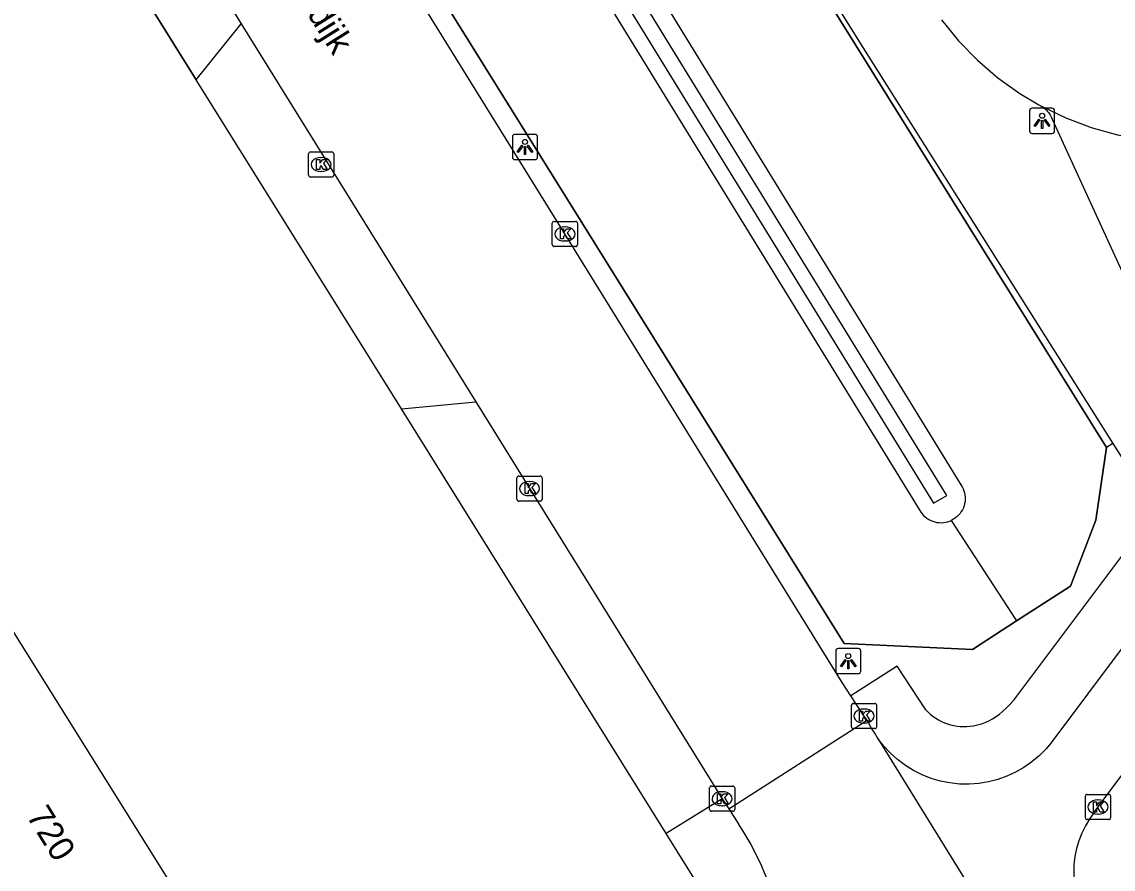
# Model space of a CAD drawing. Extents: x 158838 to 160074, y 386376 to 387776.
# Drawn here: x 159182.34 to 159225.69, y 386765.84 to 386799.5 of the extents above; entities that cross this region are included whole.
import ezdxf

# ---------------------------------------------------------------- set-up
doc = ezdxf.new("R2010")
doc.units = 0
for name, color, linetype in [('IMGEO_Berm_groen', 7, 'Continuous'), ('IMGEO_Fietspad_gesloten', 7, 'Continuous'), ('IMGEO_Groenvoorziening', 7, 'Continuous'), ('IMGEO_Hek', 7, 'Continuous'), ('IMGEO_Kolk', 7, 'Continuous'), ('IMGEO_Lichtpunt', 7, 'Continuous'), ('IMGEO_Openbare_ruimte_label', 7, 'Continuous'), ('IMGEO_OVBaan_gesloten', 7, 'Continuous'), ('IMGEO_Pand', 7, 'Continuous'), ('IMGEO_Pand_nummerreeks', 7, 'Continuous'), ('IMGEO_Rijbaan_lokaal_gesloten', 7, 'Continuous'), ('IMGEO_Rijbaan_lokaal_open', 7, 'Continuous'), ('IMGEO_Voetpad_open', 7, 'Continuous')]:
    doc.layers.add(name, color=color, linetype=linetype)

msp = doc.modelspace()

# ---------------------------------------------------------------- linework, layer by layer
at = {"layer": 'IMGEO_Berm_groen'}
for points in [[(159221.856, 386775.703), (159220.103, 386774.566), (159215.005, 386774.81), (159181.964, 386827.844)], [(159225.683, 386782.752), (159225.425, 386782.595)], [(159221.856, 386775.703), (159223.994, 386777.09), (159224.999, 386779.713), (159225.425, 386782.595)]]:
    msp.add_lwpolyline(points, dxfattribs=at)
at = {"layer": 'IMGEO_Fietspad_gesloten'}
for points in [[(159222.857, 386796.143), (159222.934, 386796.089), (159223.007, 386796.028), (159223.074, 386795.961), (159223.135, 386795.888), (159223.189, 386795.81), (159223.236, 386795.728), (159223.275, 386795.642), (159229.547, 386781.951), (159229.638, 386781.735), (159229.721, 386781.477), (159229.781, 386781.212), (159229.818, 386780.944), (159229.83, 386780.673), (159229.818, 386780.402), (159229.781, 386780.133), (159229.721, 386779.869), (159229.638, 386779.611), (159229.532, 386779.361)], [(159229.086, 386778.683), (159223.221, 386770.847), (159223.029, 386770.621), (159222.759, 386770.349), (159222.465, 386770.103), (159222.15, 386769.883), (159221.817, 386769.693), (159221.468, 386769.533), (159221.107, 386769.405), (159220.735, 386769.309), (159220.356, 386769.248), (159219.974, 386769.22), (159219.59, 386769.227), (159219.209, 386769.268), (159218.832, 386769.342), (159218.464, 386769.45), (159218.107, 386769.591), (159217.764, 386769.763), (159217.438, 386769.965), (159217.131, 386770.195), (159216.846, 386770.452), (159216.585, 386770.733), (159216.35, 386771.036)], [(159224.961, 386768.129), (159225.089, 386768.314), (159229.188, 386773.771)]]:
    msp.add_lwpolyline(points, dxfattribs=at)
msp.add_arc((159227.983, 386765.729), 3.859, 141.5421, 219.2626, dxfattribs=at)
at = {"layer": 'IMGEO_Groenvoorziening'}
for points in [[(159182.122, 386834.323), (159182.77, 386834.218), (159183.406, 386834.055), (159184.024, 386833.836), (159184.621, 386833.563), (159185.191, 386833.237), (159185.729, 386832.862), (159186.232, 386832.44), (159186.695, 386831.975), (159187.115, 386831.471), (159218.557, 386780.384), (159219.079, 386780.692), (159188.092, 386831.097), (159187.73, 386831.664), (159187.319, 386832.197), (159186.862, 386832.691), (159186.362, 386833.142), (159185.825, 386833.546), (159185.253, 386833.901), (159185.183, 386833.94)], [(159225.425, 386782.595), (159193.034, 386834.571)], [(159188.511, 386831.756), (159188.704, 386831.434), (159219.711, 386781.007), (159219.734, 386780.957), (159219.765, 386780.877), (159219.789, 386780.794), (159219.805, 386780.709), (159219.813, 386780.623), (159219.814, 386780.537), (159219.807, 386780.451), (159219.793, 386780.366), (159219.77, 386780.282), (159219.741, 386780.201), (159219.704, 386780.123), (159219.661, 386780.049), (159219.611, 386779.978), (159219.555, 386779.913), (159219.493, 386779.852), (159219.426, 386779.798), (159219.355, 386779.749), (159219.279, 386779.708), (159219.263, 386779.701)], [(159186.575, 386831.217), (159218.054, 386780.026), (159218.106, 386779.957), (159218.164, 386779.893), (159218.227, 386779.835), (159218.295, 386779.782), (159218.368, 386779.735), (159218.445, 386779.696), (159218.525, 386779.663), (159218.607, 386779.638), (159218.692, 386779.62), (159218.777, 386779.609), (159218.863, 386779.607), (159218.95, 386779.612), (159219.035, 386779.625), (159219.119, 386779.645), (159219.201, 386779.673), (159219.263, 386779.701)], [(159219.263, 386779.701), (159221.856, 386775.703)]]:
    msp.add_lwpolyline(points, dxfattribs=at)
at = {"layer": 'IMGEO_Hek'}
for points in [[(159193.034, 386834.571), (159225.425, 386782.595)], [(159181.964, 386827.844), (159215.005, 386774.81), (159220.103, 386774.566), (159221.856, 386775.703)], [(159189.265, 386797.201), (159182.052, 386808.764), (159180.897, 386809.75), (159178.798, 386810.825), (159176.512, 386811.455), (159174.154, 386811.455), (159171.857, 386810.878), (159136.254, 386788.629)], [(159197.421, 386784.127), (159189.265, 386797.201)], [(159207.941, 386767.261), (159197.421, 386784.127)], [(159225.425, 386782.595), (159224.999, 386779.713), (159223.994, 386777.09), (159221.856, 386775.703)], [(159209.388, 386764.893), (159209.317, 386765.056), (159207.941, 386767.261)]]:
    msp.add_lwpolyline(points, dxfattribs=at)
at = {"layer": 'IMGEO_Kolk'}
for p, q in [((159193.726, 386793.41), (159193.726, 386794.262)), ((159193.801, 386794.336), (159194.653, 386794.336)), ((159194.214, 386794.116), (159194.239, 386794.116)), ((159194.727, 386794.262), (159194.727, 386793.41)), ((159194.237, 386793.556), (159194.212, 386793.556)), ((159194.653, 386793.336), (159193.801, 386793.336)), ((159203.411, 386790.652), (159203.411, 386791.504)), ((159203.486, 386791.578), (159204.338, 386791.578)), ((159203.899, 386791.358), (159203.924, 386791.358)), ((159204.412, 386791.504), (159204.412, 386790.652)), ((159204.338, 386790.578), (159203.486, 386790.578)), ((159203.922, 386790.798), (159203.897, 386790.798)), ((159202.006, 386780.536), (159202.006, 386781.388)), ((159202.081, 386781.462), (159202.933, 386781.462)), ((159203.007, 386781.388), (159203.007, 386780.536)), ((159202.494, 386781.242), (159202.519, 386781.242)), ((159202.517, 386780.682), (159202.492, 386780.682)), ((159202.933, 386780.462), (159202.081, 386780.462)), ((159215.296, 386771.501), (159215.296, 386772.353)), ((159215.371, 386772.427), (159216.223, 386772.427)), ((159216.297, 386772.353), (159216.297, 386771.501)), ((159215.784, 386772.207), (159215.809, 386772.207)), ((159216.223, 386771.427), (159215.371, 386771.427)), ((159215.807, 386771.647), (159215.782, 386771.647)), ((159209.656, 386768.217), (159209.656, 386769.069)), ((159209.731, 386769.143), (159210.583, 386769.143)), ((159210.144, 386768.923), (159210.169, 386768.923)), ((159210.657, 386769.069), (159210.657, 386768.217)), ((159224.664, 386768.813), (159225.516, 386768.813)), ((159210.167, 386768.363), (159210.142, 386768.363)), ((159224.589, 386767.887), (159224.589, 386768.739)), ((159225.077, 386768.593), (159225.102, 386768.593)), ((159225.59, 386768.739), (159225.59, 386767.887)), ((159210.583, 386768.143), (159209.731, 386768.143)), ((159225.1, 386768.033), (159225.075, 386768.033)), ((159225.516, 386767.813), (159224.664, 386767.813))]:
    msp.add_line(p, q, dxfattribs=at)
for points in [[(159193.726, 386793.41), (159193.726, 386794.262)], [(159193.801, 386794.336), (159194.653, 386794.336)], [(159194.047, 386794.036), (159194.17, 386794.036), (159194.17, 386793.885), (159194.3, 386794.036), (159194.464, 386794.036), (159194.318, 386793.885), (159194.471, 386793.636), (159194.319, 386793.636), (159194.234, 386793.8), (159194.17, 386793.733), (159194.17, 386793.636), (159194.047, 386793.636), (159194.047, 386794.036)], [(159194.727, 386794.262), (159194.727, 386793.41)], [(159194.653, 386793.336), (159193.801, 386793.336)], [(159203.411, 386790.652), (159203.411, 386791.504)], [(159203.486, 386791.578), (159204.338, 386791.578)], [(159204.412, 386791.504), (159204.412, 386790.652)], [(159203.732, 386791.278), (159203.855, 386791.278), (159203.855, 386791.127), (159203.985, 386791.278), (159204.149, 386791.278), (159204.003, 386791.127), (159204.156, 386790.878), (159204.004, 386790.878), (159203.919, 386791.042), (159203.855, 386790.975), (159203.855, 386790.878), (159203.732, 386790.878), (159203.732, 386791.278)], [(159204.338, 386790.578), (159203.486, 386790.578)], [(159202.006, 386780.536), (159202.006, 386781.388)], [(159202.081, 386781.462), (159202.933, 386781.462)], [(159203.007, 386781.388), (159203.007, 386780.536)], [(159202.327, 386781.162), (159202.45, 386781.162), (159202.45, 386781.011), (159202.58, 386781.162), (159202.744, 386781.162), (159202.598, 386781.011), (159202.751, 386780.762), (159202.599, 386780.762), (159202.514, 386780.926), (159202.45, 386780.859), (159202.45, 386780.762), (159202.327, 386780.762), (159202.327, 386781.162)], [(159202.933, 386780.462), (159202.081, 386780.462)], [(159215.296, 386771.501), (159215.296, 386772.353)], [(159215.371, 386772.427), (159216.223, 386772.427)], [(159216.297, 386772.353), (159216.297, 386771.501)], [(159215.617, 386772.127), (159215.74, 386772.127), (159215.74, 386771.976), (159215.87, 386772.127), (159216.034, 386772.127), (159215.888, 386771.976), (159216.041, 386771.727), (159215.889, 386771.727), (159215.804, 386771.891), (159215.74, 386771.824), (159215.74, 386771.727), (159215.617, 386771.727), (159215.617, 386772.127)], [(159216.223, 386771.427), (159215.371, 386771.427)], [(159209.656, 386768.217), (159209.656, 386769.069)], [(159209.731, 386769.143), (159210.583, 386769.143)], [(159209.977, 386768.843), (159210.1, 386768.843), (159210.1, 386768.692), (159210.23, 386768.843), (159210.394, 386768.843), (159210.248, 386768.692), (159210.401, 386768.443), (159210.249, 386768.443), (159210.164, 386768.607), (159210.1, 386768.54), (159210.1, 386768.443), (159209.977, 386768.443), (159209.977, 386768.843)], [(159210.657, 386769.069), (159210.657, 386768.217)], [(159224.664, 386768.813), (159225.516, 386768.813)], [(159224.589, 386767.887), (159224.589, 386768.739)], [(159224.91, 386768.513), (159225.033, 386768.513), (159225.033, 386768.362), (159225.163, 386768.513), (159225.327, 386768.513), (159225.181, 386768.362), (159225.334, 386768.113), (159225.182, 386768.113), (159225.097, 386768.277), (159225.033, 386768.21), (159225.033, 386768.113), (159224.91, 386768.113), (159224.91, 386768.513)], [(159225.59, 386768.739), (159225.59, 386767.887)], [(159210.583, 386768.143), (159209.731, 386768.143)], [(159225.516, 386767.813), (159224.664, 386767.813)]]:
    msp.add_lwpolyline(points, dxfattribs=at)
for centre, start, end in [((159193.803, 386794.26), 91.552, 178.448), ((159193.803, 386794.26), 91.552, 178.448), ((159194.651, 386794.26), 1.552, 88.448), ((159194.651, 386794.26), 1.552, 88.448), ((159193.803, 386793.412), 181.552, 268.448), ((159193.803, 386793.412), 181.552, 268.448), ((159194.651, 386793.412), 271.552, 358.448), ((159194.651, 386793.412), 271.552, 358.448), ((159203.488, 386791.502), 91.552, 178.448), ((159203.488, 386791.502), 91.552, 178.448), ((159204.336, 386791.502), 1.552, 88.448), ((159204.336, 386791.502), 1.552, 88.448), ((159203.488, 386790.654), 181.552, 268.448), ((159203.488, 386790.654), 181.552, 268.448), ((159204.336, 386790.654), 271.552, 358.448), ((159204.336, 386790.654), 271.552, 358.448), ((159202.083, 386781.386), 91.552, 178.448), ((159202.083, 386781.386), 91.552, 178.448), ((159202.931, 386781.386), 1.552, 88.448), ((159202.931, 386781.386), 1.552, 88.448), ((159202.083, 386780.538), 181.552, 268.448), ((159202.083, 386780.538), 181.552, 268.448), ((159202.931, 386780.538), 271.552, 358.448), ((159202.931, 386780.538), 271.552, 358.448), ((159215.373, 386772.351), 91.552, 178.448), ((159215.373, 386772.351), 91.552, 178.448), ((159216.221, 386772.351), 1.552, 88.448), ((159216.221, 386772.351), 1.552, 88.448), ((159215.373, 386771.503), 181.552, 268.448), ((159215.373, 386771.503), 181.552, 268.448), ((159216.221, 386771.503), 271.552, 358.448), ((159216.221, 386771.503), 271.552, 358.448), ((159209.733, 386769.067), 91.552, 178.448), ((159209.733, 386769.067), 91.552, 178.448), ((159210.581, 386769.067), 1.552, 88.448), ((159210.581, 386769.067), 1.552, 88.448), ((159224.666, 386768.737), 91.552, 178.448), ((159224.666, 386768.737), 91.552, 178.448), ((159225.514, 386768.737), 1.552, 88.448), ((159225.514, 386768.737), 1.552, 88.448), ((159209.733, 386768.219), 181.552, 268.448), ((159209.733, 386768.219), 181.552, 268.448), ((159210.581, 386768.219), 271.552, 358.448), ((159210.581, 386768.219), 271.552, 358.448), ((159224.666, 386767.889), 181.552, 268.448), ((159224.666, 386767.889), 181.552, 268.448), ((159225.514, 386767.889), 271.552, 358.448), ((159225.514, 386767.889), 271.552, 358.448)]:
    msp.add_arc(centre, 0.0765, start, end, dxfattribs=at)
for centre, major_axis, ratio, start_param, end_param in [((159194.213, 386793.836), (-0.387, 0.002), 0.722429, 4.712389, 7.853982), ((159194.238, 386793.836), (-0.39, 0.002), 0.717154, 1.570796, 4.712389), ((159203.898, 386791.078), (-0.387, 0.002), 0.722429, 4.712389, 7.853982), ((159203.923, 386791.078), (-0.39, 0.002), 0.717154, 1.570796, 4.712389), ((159202.493, 386780.962), (-0.387, 0.002), 0.722429, 4.712389, 7.853982), ((159202.518, 386780.962), (-0.39, 0.002), 0.717154, 1.570796, 4.712389), ((159215.783, 386771.927), (-0.387, 0.002), 0.722429, 4.712389, 7.853982), ((159215.808, 386771.927), (-0.39, 0.002), 0.717154, 1.570796, 4.712389), ((159210.143, 386768.643), (-0.387, 0.002), 0.722429, 4.712389, 7.853982), ((159210.168, 386768.643), (-0.39, 0.002), 0.717154, 1.570796, 4.712389), ((159225.076, 386768.313), (-0.387, 0.002), 0.722429, 4.712389, 7.853982), ((159225.101, 386768.313), (-0.39, 0.002), 0.717154, 1.570796, 4.712389)]:
    msp.add_ellipse(centre, major_axis=major_axis, ratio=ratio, start_param=start_param, end_param=end_param, dxfattribs=at)
at = {"layer": 'IMGEO_Lichtpunt'}
for p, q in [((159222.372, 386795.974), (159222.372, 386795.167)), ((159222.372, 386795.974), (159222.372, 386795.167)), ((159223.274, 386796.069), (159222.466, 386796.069)), ((159223.274, 386796.069), (159222.466, 386796.069)), ((159223.368, 386795.167), (159223.368, 386795.974)), ((159223.368, 386795.167), (159223.368, 386795.974)), ((159201.828, 386794.935), (159201.828, 386794.128)), ((159201.828, 386794.935), (159201.828, 386794.128)), ((159202.73, 386795.03), (159201.922, 386795.03)), ((159202.73, 386795.03), (159201.922, 386795.03)), ((159202.824, 386794.128), (159202.824, 386794.935)), ((159202.824, 386794.128), (159202.824, 386794.935)), ((159222.466, 386795.073), (159223.274, 386795.073)), ((159222.466, 386795.073), (159223.274, 386795.073)), ((159201.922, 386794.034), (159202.73, 386794.034)), ((159201.922, 386794.034), (159202.73, 386794.034)), ((159214.67, 386774.513), (159214.67, 386773.706)), ((159214.67, 386774.513), (159214.67, 386773.706)), ((159215.572, 386774.608), (159214.764, 386774.608)), ((159215.572, 386774.608), (159214.764, 386774.608)), ((159215.666, 386773.706), (159215.666, 386774.513)), ((159215.666, 386773.706), (159215.666, 386774.513)), ((159214.764, 386773.612), (159215.572, 386773.612)), ((159214.764, 386773.612), (159215.572, 386773.612))]:
    msp.add_line(p, q, dxfattribs=at)
for points in [[(159222.746, 386795.638), (159222.785, 386795.61), (159222.597, 386795.348), (159222.559, 386795.375), (159222.746, 386795.638)], [(159222.848, 386795.59), (159222.895, 386795.59), (159222.895, 386795.268), (159222.848, 386795.268), (159222.848, 386795.59)], [(159222.958, 386795.61), (159222.996, 386795.637), (159223.183, 386795.375), (159223.144, 386795.347), (159222.958, 386795.61)], [(159202.202, 386794.599), (159202.241, 386794.571), (159202.053, 386794.309), (159202.015, 386794.336), (159202.202, 386794.599)], [(159202.304, 386794.551), (159202.351, 386794.551), (159202.351, 386794.229), (159202.304, 386794.229), (159202.304, 386794.551)], [(159202.414, 386794.571), (159202.452, 386794.598), (159202.639, 386794.336), (159202.6, 386794.308), (159202.414, 386794.571)], [(159215.044, 386774.177), (159215.083, 386774.149), (159214.895, 386773.887), (159214.857, 386773.914), (159215.044, 386774.177)], [(159215.146, 386774.129), (159215.193, 386774.129), (159215.193, 386773.807), (159215.146, 386773.807), (159215.146, 386774.129)], [(159215.256, 386774.149), (159215.294, 386774.176), (159215.481, 386773.914), (159215.442, 386773.886), (159215.256, 386774.149)]]:
    msp.add_lwpolyline(points, dxfattribs=at)
for centre in [(159222.871, 386795.772), (159202.327, 386794.733), (159215.169, 386774.311)]:
    msp.add_circle(centre, 0.0994, dxfattribs=at)
for centre, start, end in [((159222.466, 386795.974), 90, 180), ((159222.466, 386795.974), 90, 180), ((159223.274, 386795.974), 0, 90), ((159223.274, 386795.974), 0, 90), ((159201.922, 386794.935), 90, 180), ((159201.922, 386794.935), 90, 180), ((159202.73, 386794.935), 0, 90), ((159202.73, 386794.935), 0, 90), ((159222.466, 386795.167), 180, 270), ((159222.466, 386795.167), 180, 270), ((159223.274, 386795.167), 270, 0), ((159223.274, 386795.167), 270, 360), ((159201.922, 386794.128), 180, 270), ((159201.922, 386794.128), 180, 270), ((159202.73, 386794.128), 270, 0), ((159202.73, 386794.128), 270, 360), ((159214.764, 386774.513), 90, 180), ((159214.764, 386774.513), 90, 180), ((159215.572, 386774.513), 0, 90), ((159215.572, 386774.513), 0, 90), ((159214.764, 386773.706), 180, 270), ((159214.764, 386773.706), 180, 270), ((159215.572, 386773.706), 270, 0), ((159215.572, 386773.706), 270, 360)]:
    msp.add_arc(centre, 0.0946, start, end, dxfattribs=at)
at = {"layer": 'IMGEO_OVBaan_gesloten'}
msp.add_arc((159198.557, 386787.29), 36.178, 318.4599, 335.4559, dxfattribs=at)
at = {"layer": 'IMGEO_Pand'}
msp.add_lwpolyline([(159178.263, 386781.231), (159190.357, 386761.88)], dxfattribs=at)
at = {"layer": 'IMGEO_Rijbaan_lokaal_gesloten'}
for points in [[(159210.42, 386768.242), (159215.915, 386771.769)], [(159216.35, 386771.036), (159216.223, 386771.242), (159216.071, 386771.488), (159215.915, 386771.769)], [(159216.35, 386771.036), (159220.992, 386763.512)], [(159210.42, 386768.242), (159210.827, 386767.617)]]:
    msp.add_lwpolyline(points, dxfattribs=at)
msp.add_arc((159200.485, 386760.899), 12.333, 9.9741, 33.0064, dxfattribs=at)
at = {"layer": 'IMGEO_Rijbaan_lokaal_open'}
for points in [[(159215.274, 386772.727), (159214.927, 386773.26), (159203.911, 386791.078), (159196.853, 386802.486), (159190.237, 386813.13), (159189.98, 386813.56), (159188.119, 386816.595)], [(159184.396, 386809.768), (159185.669, 386808.14), (159186.192, 386807.255), (159191.052, 386799.421)], [(159218.869, 386799.586), (159219.548, 386798.751), (159220.298, 386797.981), (159221.115, 386797.28), (159221.991, 386796.655), (159222.746, 386796.204), (159222.857, 386796.143)], [(159191.052, 386799.421), (159194.344, 386794.115), (159194.994, 386793.062), (159200.369, 386784.406)], [(159231.305, 386794.999), (159231.238, 386794.984), (159230.174, 386794.795), (159229.097, 386794.702), (159228.016, 386794.706), (159226.94, 386794.807), (159225.877, 386795.003), (159224.835, 386795.293), (159223.824, 386795.675), (159222.857, 386796.143)], [(159200.369, 386784.406), (159210.158, 386768.643)], [(159215.915, 386771.769), (159215.795, 386771.927), (159215.274, 386772.727)], [(159210.158, 386768.643), (159210.42, 386768.242)]]:
    msp.add_lwpolyline(points, dxfattribs=at)
at = {"layer": 'IMGEO_Voetpad_open'}
for points in [[(159190.588, 386838.84), (159215.479, 386798.902), (159215.834, 386798.34), (159225.683, 386782.752)], [(159182.052, 386808.764), (159189.265, 386797.201)], [(159189.265, 386797.201), (159191.052, 386799.421)], [(159197.421, 386784.127), (159189.265, 386797.201)], [(159197.421, 386784.127), (159200.369, 386784.406)], [(159207.941, 386767.261), (159197.421, 386784.127)], [(159225.683, 386782.752), (159226.642, 386781.234), (159226.696, 386781.132), (159226.773, 386780.959), (159226.835, 386780.78), (159226.88, 386780.595), (159226.908, 386780.408), (159226.92, 386780.219), (159226.915, 386780.029), (159226.892, 386779.841), (159226.853, 386779.655), (159226.798, 386779.474), (159226.726, 386779.298), (159226.64, 386779.129), (159226.538, 386778.969), (159221.735, 386772.564), (159221.714, 386772.535), (159221.587, 386772.382), (159221.447, 386772.24), (159221.296, 386772.112)], [(159218.245, 386772.172), (159217.107, 386773.904), (159215.274, 386772.727)], [(159210.158, 386768.643), (159207.941, 386767.261)], [(159209.388, 386764.893), (159209.317, 386765.056), (159207.941, 386767.261)]]:
    msp.add_lwpolyline(points, dxfattribs=at)
for centre, radius, start, end in [((159219.788, 386773.632), 2.124, 223.4159, 279.5329), ((159219.743, 386773.784), 2.281, 280.0089, 312.883)]:
    msp.add_arc(centre, radius, start, end, dxfattribs=at)

# ---------------------------------------------------------------- texts
at = {"layer": 'IMGEO_Openbare_ruimte_label'}
msp.add_text('Boschdijk', height=1, rotation=302.0539, dxfattribs=at).set_placement((159191.676, 386802.98))
at = {"layer": 'IMGEO_Pand_nummerreeks'}
msp.add_text('720', height=1, rotation=301.8161, dxfattribs=at).set_placement((159182.494, 386767.964))

doc.saveas('drawing.dxf')
